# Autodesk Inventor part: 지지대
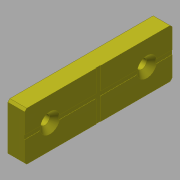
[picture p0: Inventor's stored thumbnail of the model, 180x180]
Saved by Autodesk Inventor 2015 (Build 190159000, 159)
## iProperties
Created: 2017-04
Part Number: 지지대
Material: 강철
Document SubType Name: Modeling
Designer: mduedu
Density: 7.85 g/cm^3
Appearance: 밝은 황색
Mass: 97.8484 g
Surface Area: 48.4895 cm^2
Volume: 12.4648 cm^3
Author: mduedu
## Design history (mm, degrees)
sketch "스케치1"
  geometry: L1 (23, -35)-(23, 35); L2 (0, -35)-(0, 35); L3 (0, 35)-(23, 35); L4 (0, -35)-(23, -35); 2 further points
  constraints: 8 end point, 2 parallel, 1 coincident, 1 midpoint, 1 perpendicular, 1 vertical
  dimensions: "d1" = 23 distance between parallel lines of L2 L1; "d15" = 70 distance of L1.start L1.end
extrude "돌출1" new body sketch "스케치1" distance "d2" = 8; taper "d3" = 0 deg
chamfer "모따기2" distance "d16" = 1; stored, may be unused: second distance "d17" = 2, angle "d18" = 45 deg
sketch "스케치2"
  geometry: L1 (1, -35)-(22, -35) reference; L2 (23, -34)-(23, 34) reference; L3 (22, 35)-(1, 35) reference; L4 (0, 34)-(0, -34) reference; L5 (11.5, 35)-(11.5, -35); L6 (23, 0)-(0, 0); L7 (1, -35)-(0, -34) reference; L8 (23, -34)-(22, -35) reference; L9 (22, 35)-(23, 34) reference; L10 (0, 34)-(1, 35) reference; 2 further points
  constraints: 4 end point, 4 midpoint, 1 point on line, 1 symmetric about line
  dimensions: "d7" = 12 distance from line of point (11.5, 23) L3
  node "투영된 루프1"
sketch "스케치3"
  geometry: 4 further points
  constraints: 2 coincident
hole "구멍1" sketch "스케치3" at (11.5, 23), (11.5, -23) diameter "d8" = 4.5; stored, may be unused: countersink angle "d12" = 90 deg, drill point angle "d14" = 0 deg; dims "d9" = 6, "d10" = 9.4, "d11" = 2, "d13" = 8
sketch "스케치4"
  geometry: L1 (-35, 22)-(-35, 1) reference; L2 (35, 1)-(35, 22) reference; L3 (34, 23)-(-34, 23) reference; L4 (-34, 0)-(34, 0) reference; L5 (-35, 11.5)-(35, 11.5); L6 (0, 23)-(0, 0); L7 (-35, 12.5)-(35, 12.5); L8 (-35, 10.5)-(35, 10.5); L9 (-1, 23)-(-1, 0); L10 (1, 23)-(1, 0)
  constraints: 12 end point, 8 point on line, 4 parallel, 3 midpoint, 3 perpendicular
  dimensions: "d19" = 1 distance between parallel lines of L7 L5; "d21" = 1 distance between parallel lines of L8 L5; "d22" = 1 distance between parallel lines of L9 L6; "d23" = 1 distance between parallel lines of L10 L6
extrude "돌출2" cut sketch "스케치4" distance "d24" = 0.2; taper "d25" = 0 deg
extrude "돌출3" cut sketch "스케치4" distance "d26" = 0.2; taper "d27" = 0 deg
fillet "모깎기1" dims "d28" = 0.2
node "솔리드2"
node "솔리드1"
